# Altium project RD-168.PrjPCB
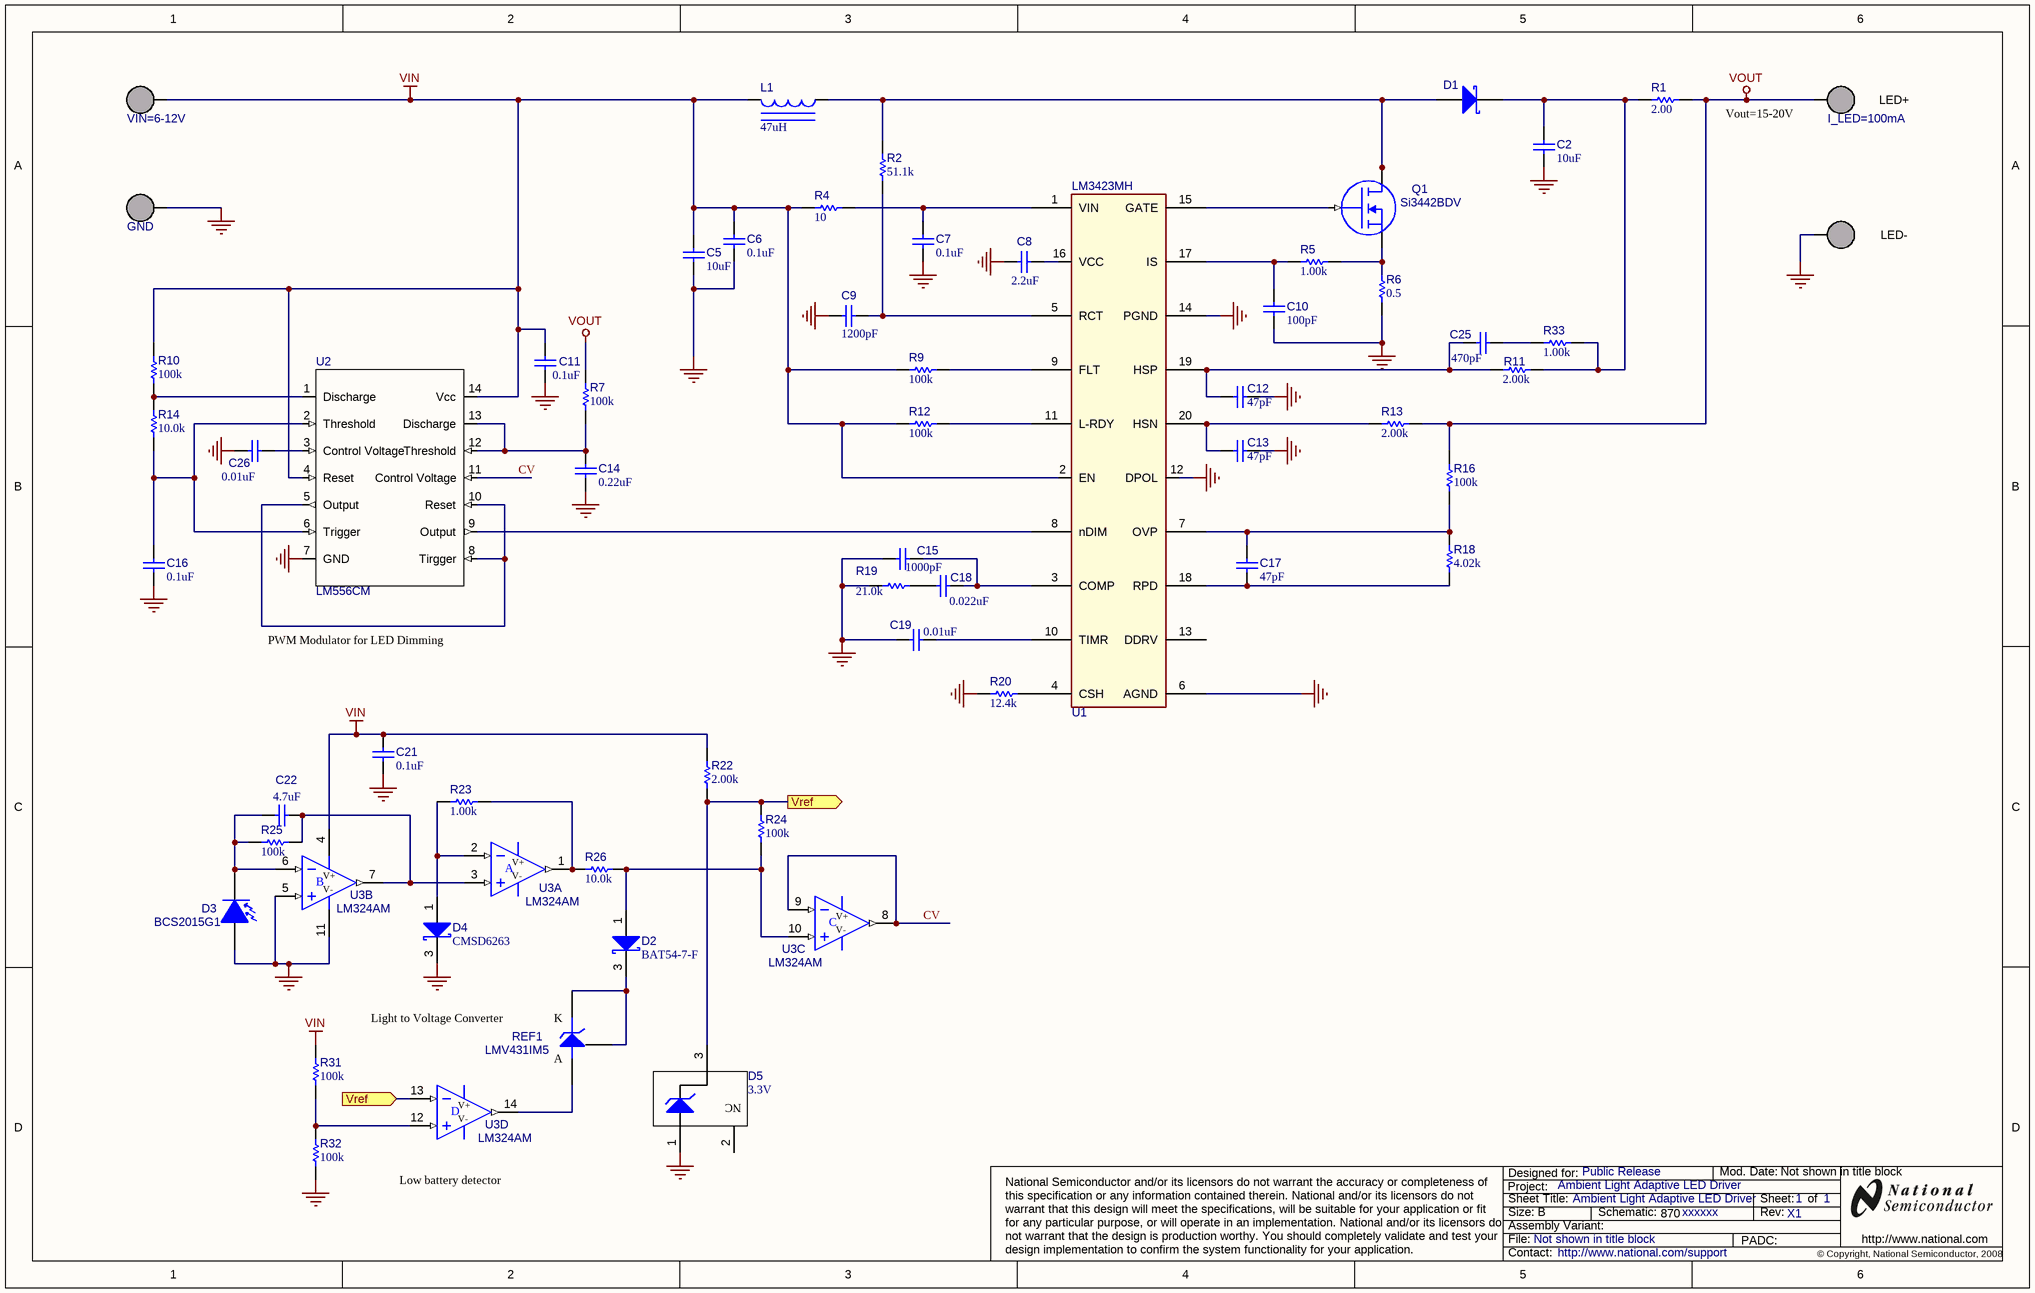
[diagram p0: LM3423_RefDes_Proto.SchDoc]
PCB_MinorRev: -001; PRJ_BasePN: xxxxxx; PRJ_Customer: Public Release; PRJ_Title: Ambient Light Adaptive LED Driver; SCH_Rev: X1; TechSupport: http://www.national.com/support
1 sheet, 59 parts. Net scope: flat (ports and power ports of the same name join across sheets).

## Sheet LM3423_RefDes_Proto.SchDoc: Ambient Light Adaptive LED Driver
size B; Date: Not shown in title block; ApprovedBy: Not shown in title block; CheckedBy: Not shown in title block; Author: Not shown in title block; CompanyName: Not shown in title block; DrawnBy: Not shown in title block; Engineer: Not shown in title block; Organization: Not shown in title block; Address1: Not shown in title block; Address2: Not shown in title block; Address3: Not shown in title block; Address4: Not shown in title block; DocumentNumber: 1; Revision: Use project parameter SCH_Rev; SheetNumber: 1; SheetTotal: 1; PageSetup: Record=PageOptions|CenterHorizontal=True|CenterVertical=True|PrintScale=0.71|XCorrection=1.00|YCorrection=1.00|PrintKind=0|BorderSize=5000000|LeftOffset=0|BottomOffset=0|Orientation=2|PaperLength=1000|PaperWidth=1000|Scale=100|PaperSource=15|PrintQuality=600|MediaType=1|DitherType=10|PaperKind=Letter|PrintScaleMode=1

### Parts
C2  value 10uF  [1206]
C5  value 10uF  [1210]  (hidden comment: C3225X7R1E106M)
C6  value 0.1uF  [1206]  (hidden comment: 12062R104K9B20D)
C7  value 0.1uF  [0805]  (hidden comment: 08053C104KAT2A)
C8  value 2.2uF  [0805]  (hidden comment: 0805YD225KAT2A)
C9  value 1200pF  [0805]  (hidden comment: 08051C122KAT2A)
C10  value 100pF  [0805]  (hidden comment: 08051A101FAT2A)
C11  value 0.1uF  [0805]  (hidden comment: 08053C104KAT2A)
C12  value 47pF  [0805]  (hidden comment: 08051A470JAT2A)
C13  value 47pF  [0805]  (hidden comment: 08051A470JAT2A)
C14  value 0.22uF  [0805]  (hidden comment: 08053C224MAT2A)
C15  value 1000pF  [0805]  (hidden comment: 08051C102KAT2A)
C16  value 0.1uF  [0805]  (hidden comment: C2012X7R1E104K)
C17  value 47pF  [0805]  (hidden comment: 08051A470KAT2A)
C18  value 0.022uF  [0805]  (hidden comment: 08051C223KAT2A)
C19  value 0.01uF  [0805]  (hidden comment: 08055C103KAT2A)
C21  value 0.1uF  [0805]  (hidden comment: 08053C104KAT2A)
C22  value 4.7uF  [0805]  (hidden comment: C2012X7R1A475M)
C25  value 470pF  [0805]  (hidden comment: 08055C471KAT2A)
C26  value 0.01uF  [0805]  (hidden comment: 08055C103KAT2A)
D1  BYS10-25-E3/TR  [SMA]  (value not drawn)
D2  BAT54-7-F  [SOT-23]
D3  BCS2015G1  [SMA]
D4  PartNumber: CMSD6263  [SOT-23]
D5  value 3.3V  [SOT-23]  (hidden comment: BZX84C3V3ET1G)
GND  (no value)  [PAD100]
I_LED=100mA  1503-2  [PAD100]  (value not drawn)
L1  value 47uH  [MSS1038]  (hidden comment: MSS1038-473MLB)
LED-  1503-2  [PAD100]  (value not drawn)
Q1  Si3442BDV  [SOT23-6]
R1  value 2.00  [0805]  (hidden comment: CRCW08052R00FNEA)
R2  value 51.1k  [0805]  (hidden comment: CRCW080551k1FKEA)
R4  value 10  [0805]  (hidden comment: CRCW080510R0JNEA)
R5  value 1.00k  [0805]  (hidden comment: CRCW08051k00FKEA)
R6  value 0.5  [1206]  (hidden comment: RL1220S-R47-F)
R7  value 100k  [0805]  (hidden comment: CRCW0805100kFKEA)
R9  value 100k  [0805]  (hidden comment: CRCW0805100kFKEA)
R10  value 100k  [0805]  (hidden comment: CRCW0805100kFKEA)
R11  value 2.00k  [0805]  (hidden comment: CRCW08052k00FKEA)
R12  value 100k  [0805]  (hidden comment: CRCW0805100kFKEA)
R13  value 2.00k  [0805]  (hidden comment: CRCW08052k00FKEA)
R14  value 10.0k  [0805]  (hidden comment: CRCW080510k0FKEA)
R16  value 100k  [0805]  (hidden comment: CRCW0805100kFKEA)
R18  value 4.02k  [0805]  (hidden comment: CRCW08054k02FKEA)
R19  value 21.0k  [0805]  (hidden comment: CRCW080521k0FKEA)
R20  value 12.4k  [0805]  (hidden comment: CRCW080512k4FKEA)
R22  value 2.00k  [0805]  (hidden comment: CRCW08052k00FKEA)
R23  value 1.00k  [0805]  (hidden comment: CRCW08051k00FKEA)
R24  value 100k  [0805]  (hidden comment: CRCW0805100kFKEA)
R25  value 100k  [0805]  (hidden comment: CRCW0805100kFKEA)
R26  value 10.0k  [0805]  (hidden comment: CRCW080510k0FKEA)
R31  value 100k  [0805]  (hidden comment: CRCW0805100kFKEA)
R32  value 100k  [0805]  (hidden comment: CRCW0805100kFKEA)
R33  value 1.00k  [0805]  (hidden comment: CRCW08051k00FKEA)
REF1  LMV431IM5  [MF05A]
U1  LM3423MH  [TSSOP-20-EP]
U2  LM556CM  [M14A]
U3  LM324AM  [M14A]  (parts A,B,C,D of 4)
VIN=6-12V  1503-2  [PAD100]  (value not drawn)

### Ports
Vref (in), Vref (out)

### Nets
GND: C2.2 C5.2 C6.1 C7.1 C8.1 C9.2 C10.2 C11.2 C12.2 C13.2 C14.2 C15.2 C16.2 C19.1 C21.2 C26.1 D3.1(A) D4.3(K) D5.1(A) GND.1 LED-.1 R6.1 R19.1 R20.2 R32.2 U1.6(AGND) U1.12(DPOL) U1.14(PGND) U2.7(GND) U3.5(IN+) U3.11(V-)
VIN: C5.1 C6.2 C11.1 C21.1 L1.2 R4.1 R9.1 R10.1 R12.1 R22.1 R31.1 U1.2(EN) U2.4(Reset) U2.14(Vcc) U3.4(V+) VIN=6-12V.1
VOUT: I_LED=100mA.1 R1.1 R7.1 R13.2 R16.1
CV: U2.11(Control_Voltage) U3.8(OUT) U3.9(IN-)
NetC2_1: C2.1 D1.2(K) R1.2 R11.2 R33.1
NetC7_2: C7.2 R4.2 U1.1(VIN)
NetC8_2: C8.2 U1.16(VCC)
NetC9_1: C9.1 R2.1 U1.5(RCT)
NetC10_1: C10.1 R5.2 U1.17(IS)
NetC12_1: C12.1 C25.2 R11.1 U1.19(HSP)
NetC13_1: C13.1 R13.1 U1.20(HSN)
NetC14_1: C14.1 R7.2 U2.12(Threshold) U2.13(Discharge)
NetC15_1: C15.1 C18.1 U1.3(COMP)
NetC16_1: C16.1 R14.2 U2.2(Threshold) U2.6(Trigger)
NetC17_1: C17.1 R18.2 U1.18(RPD)
NetC17_2: C17.2 R16.2 R18.1 U1.7(OVP)
NetC18_2: C18.2 R19.2
NetC19_2: C19.2 U1.10(TIMR)
NetC22_1: C22.1 R25.1 U3.3(IN+) U3.7(OUT)
NetC22_2: C22.2 D3.2(K) R25.2 U3.6(IN-)
NetC25_1: C25.1 R33.2
NetC26_2: C26.2 U2.3(Control_Voltage)
NetD1_1: D1.1(A) L1.1 Q1.1(D) Q1.2(D) Q1.5(D) Q1.6(D) R2.2
NetD2_1: D2.1(A) R24.2 R26.1 U3.10(IN+)
NetD2_3: D2.3(K) REF1.3(K) REF1.4(FB)
NetD4_1: D4.1(A) R23.2 U3.2(IN-)
NetD5_3: D5.3(K) R22.2 R24.1 U3.13(IN-) ; port Vref
NetQ1_3: Q1.3(G) U1.15(GATE)
NetQ1_4: Q1.4(S) R5.1 R6.2
NetR9_2: R9.2 U1.9(FLT)
NetR10_2: R10.2 R14.1 U2.1(Discharge)
NetR12_2: R12.2 U1.11(L-RDY)
NetR20_1: R20.1 U1.4(CSH)
NetR23_1: R23.1 R26.2 U3.1(OUT)
NetR31_2: R31.2 R32.1 U3.12(IN+)
NetREF1_5: REF1.5(A) U3.14(OUT)
NetU1_8: U1.8(nDIM) U2.9(Output)
NetU2_5: U2.5(Output) U2.8(Tirgger) U2.10(Reset)

Not connected (* = marked no-connect by the designer): D5 2(NC); U1 13(DDRV)

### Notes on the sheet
- LED+
- Vout=15-20V
- LED-
- PWM Modulator for LED Dimming
- Light to Voltage Converter
- Low battery detector

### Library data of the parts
C2 = Capacitor: Manufacturer: Taiyo Yuden; PartNumber: TMK316BJ106ML-T; Polarized: N; Characteristics: Ceramic, X5R, 25V, 20%
C5 = C3225X7R1E106M: Capacitor; Manufacturer: TDK; ESR_Ohm: 0.0027; IRMS_A: 3; Polarized: N; TaMax_C: 125; TaMin_C: -55; Tolerance_%: 20; VDC_V: 25; Cap_F: 10.0E-6; Value1: 0.0027Ohm; Value2: 25V; Dielectric: X7R; Characteristics: Ceramic, X7R, 25V, 20%
C6 = 12062R104K9B20D: Capacitor; Manufacturer: Yageo America; ESR_Ohm: 0; Polarized: N; Tolerance_%: 10; VDC_V: 50; Cap_F: 100.0E-9; Value1: 0Ohm; Value2: 50V; Dielectric: X7R; Characteristics: Ceramic, X7R, 50V, 10%
C7 C11 C21 = 08053C104KAT2A: Capacitor; Manufacturer: AVX; ESR_Ohm: 0.28; Polarized: N; TaMax_C: 125; TaMin_C: -55; Tolerance_%: 10; VDC_V: 25; Cap_F: 100.0E-9; Value1: 0.28Ohm; Value2: 25V; Dielectric: X7R; Characteristics: Ceramic, X7R, 25V, 10%
C8 = 0805YD225KAT2A: Capacitor; Manufacturer: AVX; ESR_Ohm: 0.009; Polarized: N; TaMax_C: 85; TaMin_C: -55; Tolerance_%: 10; VDC_V: 16; Cap_F: 2.2E-6; Value1: 0.009Ohm; Value2: 16V; Dielectric: X5R; Characteristics: Ceramic, X5R, 16V, 10%
C9 = 08051C122KAT: Capacitor; Manufacturer: AVX; ESR_Ohm: 0; Polarized: N; TaMax_C: 125; TaMin_C: -55; Tolerance_%: 10; VDC_V: 100; Cap_F: 1.2E-9; Value1: 0Ohm; Value2: 100V; Dielectric: X7R; Characteristics: Ceramic, X7R, 100V, 10%
C10 = 08051A101FAT2A: Capacitor; Manufacturer: AVX; ESR_Ohm: 0.356; Polarized: N; TaMax_C: 125; TaMin_C: -55; Tolerance_%: 1; VDC_V: 100; Cap_F: 100.0E-12; Value1: 0.356Ohm; Value2: 100V; Dielectric: C0G/NP0; Characteristics: Ceramic, C0G/NP0, 100V, 1%
C12 C13 = 08051A470JAT2A: Capacitor; Manufacturer: AVX; ESR_Ohm: 0.566; Polarized: N; TaMax_C: 125; TaMin_C: -55; Tolerance_%: 5; VDC_V: 100; Cap_F: 47.0E-12; Value1: 0.566Ohm; Value2: 100V; Dielectric: C0G/NP0; Characteristics: Ceramic, C0G/NP0, 100V, 5%
C14 = 08053C224MAT2A: Capacitor; Manufacturer: AVX; ESR_Ohm: 0.016; Polarized: N; TaMax_C: 125; TaMin_C: -55; Tolerance_%: 20; VDC_V: 25; Cap_F: 220.0E-9; Value1: 0.016Ohm; Value2: 25V; Dielectric: X7R; Characteristics: Ceramic, X7R, 25V, 20%
C15 = 08051C102KAT2A: Capacitor; Manufacturer: AVX; ESR_Ohm: 0.29; Polarized: N; TaMax_C: 125; TaMin_C: -55; Tolerance_%: 10; VDC_V: 100; Cap_F: 1.0E-9; Value1: 0.29Ohm; Value2: 100V; Dielectric: X7R; Characteristics: Ceramic, X7R, 100V, 10%
C16 = C2012X7R1E104K: Capacitor; Manufacturer: TDK; Polarized: N; TaMax_C: 125; TaMin_C: -55; Tolerance_%: 10; VDC_V: 25; Cap_F: 100.0E-9; Value1: Ohm; Value2: 25V; Dielectric: X7R; Characteristics: Ceramic, X7R, 25V, 10%
C17 = 08051A470KAT2A: Capacitor; Manufacturer: AVX; ESR_Ohm: 0.566; Polarized: N; TaMax_C: 125; TaMin_C: -55; Tolerance_%: 10; VDC_V: 100; Cap_F: 47.0E-12; Value1: 0.566Ohm; Value2: 100V; Dielectric: C0G/NP0; Characteristics: Ceramic, C0G/NP0, 100V, 10%
C18 = 08051C223KAT2A: Capacitor; Manufacturer: AVX; ESR_Ohm: 0.052; Polarized: N; TaMax_C: 125; TaMin_C: -55; Tolerance_%: 10; VDC_V: 100; Cap_F: 22.0E-9; Value1: 0.052Ohm; Value2: 100V; Dielectric: X7R; Characteristics: Ceramic, X7R, 100V, 10%
C19 C26 = 08055C103KAT: Capacitor; Manufacturer: AVX; ESR_Ohm: 0; Polarized: N; TaMax_C: 125; TaMin_C: -55; Tolerance_%: 10; VDC_V: 50; Cap_F: 10.0E-9; Value1: 0Ohm; Value2: 50V; Dielectric: X7R; Characteristics: Ceramic, X7R, 50V, 10%
C22 = C2012X7R1A475M: Capacitor; Manufacturer: TDK; Polarized: N; TaMax_C: 125; TaMin_C: -55; Tolerance_%: 20; VDC_V: 10; Cap_F: 4.7E-6; Value1: Ohm; Value2: 10V; Dielectric: X7R; Characteristics: Ceramic, X7R, 10V, 20%
C25 = 08055C471KAT2A: Capacitor; Manufacturer: AVX; ESR_Ohm: 0.454; Polarized: N; TaMax_C: 125; TaMin_C: -55; Tolerance_%: 10; VDC_V: 50; Cap_F: 470.0E-12; Value1: 0.454Ohm; Value2: 50V; Dielectric: X7R; Characteristics: Ceramic, X7R, 50V, 10%
D1 = BYS10-25-E3/TR: Schottky Diode; Manufacturer: Vishay-Semiconductor; Vf_V: 0.5; Value: 0.5V; Io_A: 1.5; Value1: 1.5A; Vr_V: 25; Value2: 25V; TJmax_C: 150; Characteristics: Vr = 25V, Io = 1.5A, Vf = 0.5V
D2 = BAT54-7-F: Schottky Barrier Diode; Manufacturer: Diodes Inc.; Characteristics: Vr = 30V, Io = 0.2A, Vf = 0.65V; Vf_V: 0.65; Value: 0.65V; Io_A: 0.2; Value1: 0.2A; Vr_V: 30; Value2: 30V; TJmax_C: 125
D3 = A10190: Light Emitting Diode; Manufacturer: TDK; CompType: Photodiode
D4 = BAT46: Schottky Barrier Diode; Manufacturer: Central Semiconductor; Vf_V: 0.24; Value: 0.24V; Io_A: 0.2; Value1: 0.2A; Vr_V: 30; Value2: 30V; TJmax_C: 125; RJC_CperW: 0; Characteristics: Vr = 70V, Vf = 0.41V
D5 = BZX84C3V3ET1G: Manufacturer: ON Semiconductor; CompType: Zener; Power_W: 0.225; Vz: 3.3; RJA_CperW: 556; Characteristics: 0.225W
GND I_LED=100mA LED- VIN=6-12V = 1503-2: Terminal, Turret, TH, Double; Manufacturer: Keystone Electronics; CompType: Turret Terminal
L1 = MSS1038-473MLB: Magnetic-Core Inductor; Manufacturer: Coilcraft Inc.; Ind_H: 47.0E-6; DCR_Ohm: 0.128; Imax_A: 1.6; Material: Ferrite; Value1: 0.128Ohm; Value2: 1.6A; Characteristics: Shielded Drum Core, 1.6A, 0.128 Ohm
Q1 = FET-N_TSOP6: Logic Level, Single N-Channel MOSFET Power Trench; Manufacturer: Vishay; Value: 30V
R1 = CRCW08052R00FNEA: Resistor; Manufacturer: Vishay-Dale; Tolerance_%: 1; VDC_V: 150; Power_W: 0.125; Res_Ohm: 2; Value_Code: 2R00; Value1: 1%; Value2: 0.125W; Characteristics: 1%, 0.125W; EIA_Code: E96
R2 = CRCW080551k1FKEA: Resistor; Manufacturer: Vishay-Dale; Tolerance_%: 1; VDC_V: 150; Power_W: 0.125; Res_Ohm: 51100; Value_Code: 51k1; Value1: 1%; Value2: 0.125W; Characteristics: 1%, 0.125W; EIA_Code: E96
R4 = CRCW080510R0JNEA: Resistor; Manufacturer: Vishay-Dale; Tolerance_%: 5; VDC_V: 150; Power_W: 0.125; Value_Code: 10R0; Value1: 5%; Value2: 0.125W; Characteristics: 5%, 0.125W; EIA_Code: E24
R5 R23 R33 = CRCW08051k00FKEA: Resistor; Manufacturer: Vishay-Dale; Tolerance_%: 1; VDC_V: 150; Power_W: 0.125; Res_Ohm: 1000; Value_Code: 1k00; Value1: 1%; Value2: 0.125W; Characteristics: 1%, 0.125W; EIA_Code: E96
R6 = RL1220S-R47-F: Resistor; Manufacturer: Susumu Co; Tolerance_%: 1; VDC_V: 200; Power_W: 0.25; Value_Code: 0R5; Value1: 1%; Value2: 0.25W; Characteristics: 1%, 0.25W
R7 R9 R10 R12 R16 R24 R25 R31 R32 = CRCW0805100kFKEA: Resistor; Manufacturer: Vishay-Dale; Tolerance_%: 1; VDC_V: 150; Power_W: 0.125; Res_Ohm: 100000; Value1: 1%; Value2: 0.125W; Characteristics: 1%, 0.125W; EIA_Code: E96
R11 R13 R22 = CRCW08052k00FKEA: Resistor; Manufacturer: Vishay-Dale; Tolerance_%: 1; VDC_V: 150; Power_W: 0.125; Res_Ohm: 2000; Value_Code: 2k00; Value1: 1%; Value2: 0.125W; Characteristics: 1%, 0.125W; EIA_Code: E96
R14 R26 = CRCW080510k0FKEA: Resistor; Manufacturer: Vishay-Dale; Tolerance_%: 1; VDC_V: 150; Power_W: 0.125; Res_Ohm: 10000; Value_Code: 10k0; Value1: 1%; Value2: 0.125W; Characteristics: 1%, 0.125W; EIA_Code: E96
R18 = CRCW08054k02FKEA: Resistor; Manufacturer: Vishay-Dale; Tolerance_%: 1; VDC_V: 150; Power_W: 0.125; Res_Ohm: 4020; Value_Code: 4k02; Value1: 1%; Value2: 0.125W; Characteristics: 1%, 0.125W; EIA_Code: E96
R19 = CRCW080521k0FKEA: Resistor; Manufacturer: Vishay-Dale; Tolerance_%: 1; VDC_V: 150; Power_W: 0.125; Res_Ohm: 21000; Value_Code: 21k0; Value1: 1%; Value2: 0.125W; Characteristics: 1%, 0.125W; EIA_Code: E96
R20 = CRCW080512k4FKEA: Resistor; Manufacturer: Vishay-Dale; Tolerance_%: 1; VDC_V: 150; Power_W: 0.125; Res_Ohm: 12400; Value_Code: 12k4; Value1: 1%; Value2: 0.125W; Characteristics: 1%, 0.125W; EIA_Code: E96
REF1 = LMV431IM5: Low-Voltage (1.24V) Adjustable Precision Shunt Regulators; Manufacturer: National Semiconductor; Base_PN: LMV431; CompType: Voltage Reference
U1 = LM3423_4: Manufacturer: National Semiconductor; Characteristics: N-Channel Controllers for Constant Current LED Drivers
U2 = LM556: N-Channel Controllers for Constant Current LED Drivers; Manufacturer: National Semiconductor; Characteristics: Dual Timer
U3 = LM324AM: Low Power Quad Op Amp; Manufacturer: National Semiconductor; CompType: OpAmp IC; TaMin_C: 0.0; TaMax_C: 70.0; Characteristics: Low Power Quad Operational Amplifier

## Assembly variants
-100A: all parts fitted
